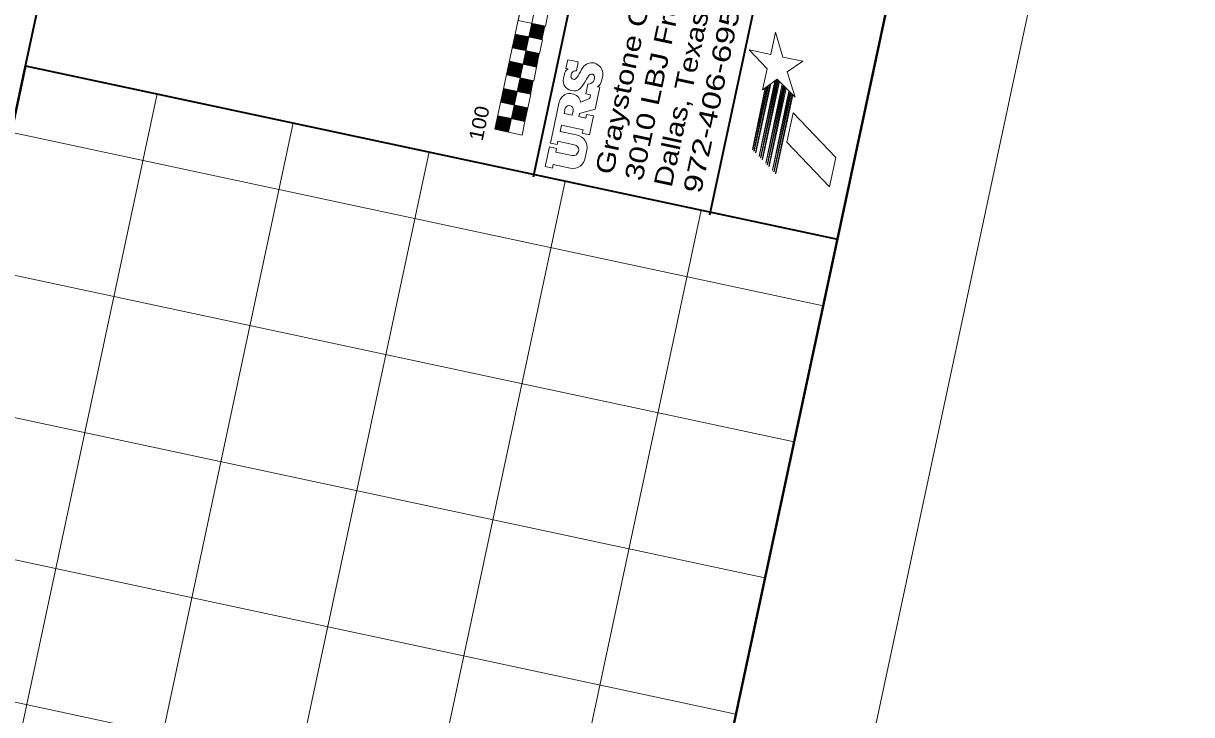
# Model space of a CAD drawing. Extents: x 2363411 to 2369126, y 6976878 to 6988319.
# Drawn here: x 2368286 to 2369126, y 6986411 to 6986908 of the extents above; entities that cross this region are included whole.
import ezdxf
from ezdxf.enums import TextEntityAlignment as Align

# ---------------------------------------------------------------- set-up
doc = ezdxf.new("R2010")
doc.units = 0
doc.header["$LTSCALE"] = 2
for name, color, linetype, lineweight in [('40', 7, 'Continuous', 13), ('62', 7, 'Continuous', 13), ('63', 7, 'Continuous', 13)]:
    doc.layers.add(name, color=color, linetype=linetype, lineweight=lineweight)

msp = doc.modelspace()

# ---------------------------------------------------------------- linework, layer by layer
at = {"layer": '40'}
for p, q in [((2367492.078, 6986997.24), (2368861.236, 6986704.691)), ((2367471.182, 6986899.443), (2368840.34, 6986606.896)), ((2368382.492, 6986857.104), (2366502.254, 6978057.311)), ((2368480.289, 6986836.208), (2366600.051, 6978036.415)), ((2368578.086, 6986815.312), (2366697.848, 6978015.519)), ((2367450.286, 6986801.645), (2368819.444, 6986509.099)), ((2368675.884, 6986794.415), (2366795.645, 6977994.623)), ((2368773.68, 6986773.519), (2366893.442, 6977973.727)), ((2367429.39, 6986703.849), (2368798.548, 6986411.302)), ((2367408.493, 6986606.051), (2368777.652, 6986313.505))]:
    msp.add_line(p, q, dxfattribs=at)
at = {"layer": '62', "lineweight": 35}
for p, q in [((2368287.795, 6986877.338), (2368423.826, 6987513.987)), ((2368788.776, 6987433.781), (2368652.739, 6986797.1)), ((2368862.364, 6987157.099), (2368779.65, 6986769.983)), ((2368287.795, 6986877.338), (2368871.478, 6986752.623))]:
    msp.add_line(p, q, dxfattribs=at)
at = {"layer": '62'}
for p, q in [((2369126.202, 6987466.173), (2366932.108, 6977197.487)), ((2368625.251, 6986831.589), (2368708.843, 6987222.813)), ((2368635.032, 6986829.5), (2368718.624, 6987220.723)), ((2368649.671, 6986897.96), (2368651.761, 6986907.742)), ((2368650.16, 6986897.857), (2368652.25, 6986907.637)), ((2368650.649, 6986897.751), (2368652.739, 6986907.534)), ((2368651.138, 6986897.648), (2368653.228, 6986907.429)), ((2368651.627, 6986897.542), (2368653.717, 6986907.324)), ((2368652.116, 6986897.439), (2368654.206, 6986907.22)), ((2368652.605, 6986897.334), (2368654.695, 6986907.116)), ((2368653.094, 6986897.229), (2368655.184, 6986907.011)), ((2368653.583, 6986897.124), (2368655.673, 6986906.906)), ((2368654.072, 6986897.02), (2368656.162, 6986906.802)), ((2368654.561, 6986896.916), (2368656.651, 6986906.698)), ((2368655.05, 6986896.812), (2368657.14, 6986906.593)), ((2368655.539, 6986896.706), (2368657.629, 6986906.489)), ((2368656.028, 6986896.603), (2368658.118, 6986906.385)), ((2368656.518, 6986896.498), (2368658.608, 6986906.279)), ((2368657.007, 6986896.394), (2368659.097, 6986906.175)), ((2368657.495, 6986896.289), (2368659.586, 6986906.07)), ((2368657.984, 6986896.184), (2368660.075, 6986905.966)), ((2368658.473, 6986896.081), (2368660.564, 6986905.861)), ((2368658.963, 6986895.975), (2368661.053, 6986905.757)), ((2368637.801, 6986890.269), (2368639.89, 6986900.051)), ((2368638.29, 6986890.165), (2368640.38, 6986899.946)), ((2368638.781, 6986890.06), (2368640.87, 6986899.841)), ((2368639.27, 6986889.956), (2368641.358, 6986899.736)), ((2368639.758, 6986889.851), (2368641.848, 6986899.632)), ((2368639.88, 6986900.053), (2368649.66, 6986897.963)), ((2368640.247, 6986889.747), (2368642.337, 6986899.528)), ((2368640.735, 6986889.643), (2368642.826, 6986899.423)), ((2368641.225, 6986889.538), (2368643.315, 6986899.318)), ((2368641.714, 6986889.434), (2368643.804, 6986899.215)), ((2368642.203, 6986889.33), (2368644.293, 6986899.109)), ((2368642.692, 6986889.224), (2368644.782, 6986899.006)), ((2368643.18, 6986889.12), (2368645.272, 6986898.901)), ((2368643.67, 6986889.015), (2368645.76, 6986898.796)), ((2368644.159, 6986888.912), (2368646.249, 6986898.691)), ((2368644.648, 6986888.806), (2368646.738, 6986898.587)), ((2368645.137, 6986888.702), (2368647.227, 6986898.483)), ((2368645.626, 6986888.598), (2368647.716, 6986898.378)), ((2368646.115, 6986888.493), (2368648.205, 6986898.273)), ((2368646.604, 6986888.389), (2368648.694, 6986898.17)), ((2368647.093, 6986888.285), (2368649.183, 6986898.064)), ((2368649.659, 6986897.964), (2368659.44, 6986895.874)), ((2368649.659, 6986897.963), (2368659.441, 6986895.874)), ((2368637.79, 6986890.272), (2368647.569, 6986888.182)), ((2368645.815, 6986878.331), (2368647.906, 6986888.111)), ((2368646.305, 6986878.225), (2368648.395, 6986888.007)), ((2368646.793, 6986878.121), (2368648.884, 6986887.903)), ((2368647.282, 6986878.017), (2368649.373, 6986887.798)), ((2368647.772, 6986877.912), (2368649.862, 6986887.694)), ((2368648.26, 6986877.807), (2368650.352, 6986887.589)), ((2368648.75, 6986877.703), (2368650.84, 6986887.483)), ((2368649.239, 6986877.598), (2368651.329, 6986887.38)), ((2368649.727, 6986877.494), (2368651.818, 6986887.275)), ((2368650.217, 6986877.389), (2368652.307, 6986887.171)), ((2368650.706, 6986877.286), (2368652.797, 6986887.066)), ((2368651.195, 6986877.18), (2368653.284, 6986886.962)), ((2368651.684, 6986877.077), (2368653.773, 6986886.859)), ((2368652.172, 6986876.97), (2368654.262, 6986886.753)), ((2368652.662, 6986876.866), (2368654.752, 6986886.648)), ((2368653.152, 6986876.762), (2368655.242, 6986886.544)), ((2368653.641, 6986876.658), (2368655.73, 6986886.439)), ((2368654.13, 6986876.553), (2368656.219, 6986886.336)), ((2368654.62, 6986876.448), (2368656.709, 6986886.23)), ((2368655.108, 6986876.344), (2368657.198, 6986886.127)), ((2368633.944, 6986870.639), (2368636.036, 6986880.419)), ((2368634.434, 6986870.534), (2368636.524, 6986880.315)), ((2368634.924, 6986870.429), (2368637.014, 6986880.21)), ((2368635.414, 6986870.326), (2368637.504, 6986880.105)), ((2368635.699, 6986880.492), (2368645.48, 6986878.401)), ((2368635.902, 6986870.22), (2368637.991, 6986880.001)), ((2368636.391, 6986870.117), (2368638.48, 6986879.898)), ((2368636.88, 6986870.012), (2368638.97, 6986879.793)), ((2368637.369, 6986869.907), (2368639.459, 6986879.689)), ((2368637.858, 6986869.804), (2368639.948, 6986879.584)), ((2368638.347, 6986869.699), (2368640.436, 6986879.479)), ((2368638.836, 6986869.594), (2368640.925, 6986879.375)), ((2368639.325, 6986869.489), (2368641.415, 6986879.27)), ((2368639.814, 6986869.385), (2368641.904, 6986879.166)), ((2368640.303, 6986869.281), (2368642.393, 6986879.061)), ((2368640.792, 6986869.176), (2368642.882, 6986878.956)), ((2368641.281, 6986869.072), (2368643.371, 6986878.853)), ((2368641.77, 6986868.968), (2368643.86, 6986878.748)), ((2368642.258, 6986868.862), (2368644.348, 6986878.643)), ((2368642.747, 6986868.759), (2368644.838, 6986878.538)), ((2368643.236, 6986868.653), (2368645.326, 6986878.434)), ((2368645.48, 6986878.402), (2368655.26, 6986876.312)), ((2368645.48, 6986878.401), (2368655.261, 6986876.312)), ((2368633.61, 6986870.71), (2368643.391, 6986868.62)), ((2368641.484, 6986858.802), (2368643.574, 6986868.581)), ((2368641.973, 6986858.697), (2368644.063, 6986868.477)), ((2368642.463, 6986858.593), (2368644.551, 6986868.372)), ((2368642.951, 6986858.488), (2368645.041, 6986868.268)), ((2368643.441, 6986858.384), (2368645.53, 6986868.163)), ((2368643.93, 6986858.279), (2368646.019, 6986868.059)), ((2368644.418, 6986858.175), (2368646.508, 6986867.954)), ((2368644.908, 6986858.07), (2368646.997, 6986867.85)), ((2368645.396, 6986857.966), (2368647.488, 6986867.746)), ((2368645.886, 6986857.861), (2368647.974, 6986867.641)), ((2368646.375, 6986857.757), (2368648.463, 6986867.537)), ((2368646.864, 6986857.653), (2368648.952, 6986867.432)), ((2368674.504, 6986868.119), (2368675.201, 6986871.38)), ((2368680.139, 6986870.917), (2368679.996, 6986870.246)), ((2368696.757, 6986867.48), (2368696.969, 6986868.663)), ((2368702.813, 6986870.319), (2368702.117, 6986867.058)), ((2368629.615, 6986851.112), (2368631.704, 6986860.892)), ((2368630.104, 6986851.007), (2368632.193, 6986860.787)), ((2368630.594, 6986850.902), (2368632.682, 6986860.683)), ((2368631.083, 6986850.798), (2368633.172, 6986860.578)), ((2368631.519, 6986860.931), (2368641.3, 6986858.842)), ((2368631.572, 6986850.692), (2368633.66, 6986860.473)), ((2368632.06, 6986850.588), (2368634.149, 6986860.369)), ((2368632.549, 6986850.484), (2368634.639, 6986860.265)), ((2368633.038, 6986850.38), (2368635.127, 6986860.161)), ((2368633.526, 6986850.276), (2368635.617, 6986860.055)), ((2368634.015, 6986850.171), (2368636.106, 6986859.952)), ((2368634.505, 6986850.067), (2368636.594, 6986859.847)), ((2368634.993, 6986849.962), (2368637.084, 6986859.743)), ((2368635.483, 6986849.857), (2368637.573, 6986859.638)), ((2368635.971, 6986849.752), (2368638.062, 6986859.533)), ((2368636.46, 6986849.649), (2368638.551, 6986859.428)), ((2368636.95, 6986849.543), (2368639.04, 6986859.324)), ((2368637.438, 6986849.439), (2368639.529, 6986859.22)), ((2368637.928, 6986849.335), (2368640.018, 6986859.115)), ((2368638.417, 6986849.231), (2368640.507, 6986859.01)), ((2368647.353, 6986857.548), (2368649.441, 6986867.328)), ((2368647.842, 6986857.443), (2368649.931, 6986867.224)), ((2368648.332, 6986857.34), (2368650.42, 6986867.119)), ((2368648.82, 6986857.234), (2368650.91, 6986867.014)), ((2368649.309, 6986857.131), (2368651.398, 6986866.909)), ((2368649.798, 6986857.025), (2368651.887, 6986866.805)), ((2368650.287, 6986856.921), (2368652.377, 6986866.7)), ((2368650.777, 6986856.816), (2368652.865, 6986866.596)), ((2368629.431, 6986851.15), (2368639.21, 6986849.06)), ((2368638.906, 6986849.126), (2368640.996, 6986858.907)), ((2368641.3, 6986858.841), (2368651.082, 6986856.751)), ((2368641.301, 6986858.839), (2368651.081, 6986856.749)), ((2368637.544, 6986839.189), (2368639.633, 6986848.969)), ((2368638.033, 6986839.085), (2368640.122, 6986848.863)), ((2368638.522, 6986838.98), (2368640.612, 6986848.76)), ((2368639.011, 6986838.876), (2368641.1, 6986848.655)), ((2368639.5, 6986838.771), (2368641.59, 6986848.552)), ((2368639.989, 6986838.668), (2368642.079, 6986848.446)), ((2368640.478, 6986838.561), (2368642.567, 6986848.342)), ((2368640.967, 6986838.458), (2368643.057, 6986848.236)), ((2368641.456, 6986838.353), (2368643.545, 6986848.132)), ((2368641.945, 6986838.248), (2368644.034, 6986848.029)), ((2368642.434, 6986838.144), (2368644.524, 6986847.924)), ((2368642.924, 6986838.04), (2368645.012, 6986847.819)), ((2368643.413, 6986837.935), (2368645.502, 6986847.715)), ((2368643.903, 6986837.83), (2368645.992, 6986847.61)), ((2368644.39, 6986837.725), (2368646.481, 6986847.507)), ((2368644.88, 6986837.622), (2368646.97, 6986847.4)), ((2368645.369, 6986837.516), (2368647.459, 6986847.297)), ((2368645.859, 6986837.413), (2368647.947, 6986847.192)), ((2368646.347, 6986837.307), (2368648.436, 6986847.088)), ((2368646.836, 6986837.203), (2368648.925, 6986846.984)), ((2368674.979, 6986843.05), (2368675.766, 6986846.731)), ((2368625.672, 6986831.498), (2368627.764, 6986841.28)), ((2368626.164, 6986831.395), (2368628.253, 6986841.175)), ((2368626.652, 6986831.289), (2368628.742, 6986841.071)), ((2368627.141, 6986831.186), (2368629.231, 6986840.965)), ((2368627.342, 6986841.369), (2368637.121, 6986839.279)), ((2368627.63, 6986831.08), (2368629.72, 6986840.861)), ((2368628.119, 6986830.977), (2368630.209, 6986840.756)), ((2368628.608, 6986830.871), (2368630.698, 6986840.652)), ((2368629.097, 6986830.767), (2368631.187, 6986840.548)), ((2368629.586, 6986830.663), (2368631.676, 6986840.443)), ((2368630.075, 6986830.558), (2368632.165, 6986840.338)), ((2368630.564, 6986830.453), (2368632.654, 6986840.234)), ((2368631.053, 6986830.349), (2368633.142, 6986840.13)), ((2368631.542, 6986830.244), (2368633.631, 6986840.026)), ((2368632.031, 6986830.141), (2368634.12, 6986839.921)), ((2368632.52, 6986830.035), (2368634.609, 6986839.817)), ((2368633.009, 6986829.932), (2368635.099, 6986839.713)), ((2368633.498, 6986829.827), (2368635.587, 6986839.608)), ((2368633.986, 6986829.722), (2368636.077, 6986839.504)), ((2368634.475, 6986829.618), (2368636.565, 6986839.398)), ((2368634.964, 6986829.513), (2368637.054, 6986839.295)), ((2368637.121, 6986839.279), (2368646.902, 6986837.19)), ((2368625.251, 6986831.589), (2368635.032, 6986829.5)), ((2368685.324, 6986815.762), (2368685.504, 6986816.604)), ((2368691.346, 6986816.633), (2368690.183, 6986811.205))]:
    msp.add_line(p, q, dxfattribs=at)
at = {"layer": '62', "lineweight": 40}
for p, q in [((2369007.509, 6987389.272), (2366855.207, 6977316.18)), ((2368287.795, 6986877.338), (2368278.342, 6986833.097))]:
    msp.add_line(p, q, dxfattribs=at)
at = {"layer": '62'}
for points in [[(2368661.531, 6986905.653), (2368663.62, 6986915.434), (2368644.059, 6986919.615), (2368641.97, 6986909.833)], [(2368808.187, 6986888.668), (2368820.942, 6986874.996), (2368817.737, 6986859.988), (2368828.121, 6986867.634), (2368841.046, 6986854.66), (2368835.463, 6986872.979), (2368846.561, 6986880.469), (2368832.247, 6986883.526), (2368826.968, 6986901.435), (2368823.547, 6986885.386)], [(2368657.352, 6986886.093), (2368659.441, 6986895.874), (2368639.88, 6986900.053), (2368637.79, 6986890.272)], [(2368653.172, 6986866.532), (2368655.261, 6986876.312), (2368635.699, 6986880.492), (2368633.61, 6986870.71)], [(2368816.227, 6986811.126), (2368827.967, 6986867.489), (2368828.121, 6986867.62), (2368828.663, 6986867.072), (2368816.401, 6986810.989)], [(2368648.992, 6986846.97), (2368651.082, 6986856.751), (2368631.519, 6986860.931), (2368629.431, 6986851.15)], [(2368810.447, 6986817.185), (2368819.696, 6986861.415), (2368820.449, 6986861.997), (2368810.613, 6986817.048)], [(2368811.534, 6986816.051), (2368821.24, 6986862.563), (2368822.028, 6986863.132), (2368811.669, 6986815.897)], [(2368812.7, 6986814.827), (2368822.945, 6986863.816), (2368823.715, 6986864.377), (2368812.857, 6986814.709)], [(2368815.158, 6986812.266), (2368826.431, 6986866.383), (2368827.314, 6986867.015), (2368815.319, 6986812.124)], [(2368817.404, 6986809.926), (2368829.219, 6986866.538), (2368829.849, 6986865.898), (2368817.565, 6986809.809)], [(2368819.966, 6986807.229), (2368831.821, 6986863.928), (2368832.428, 6986863.316), (2368820.111, 6986807.089)], [(2368821.033, 6986806.082), (2368832.902, 6986862.826), (2368833.496, 6986862.234), (2368821.191, 6986805.966)], [(2368822.195, 6986804.891), (2368834.069, 6986861.652), (2368834.669, 6986861.045), (2368822.363, 6986804.749)], [(2368824.769, 6986802.194), (2368836.652, 6986859.065), (2368837.223, 6986858.483), (2368824.921, 6986802.053)], [(2368825.816, 6986801.057), (2368837.738, 6986857.981), (2368838.301, 6986857.404), (2368825.986, 6986800.92)], [(2368827.002, 6986799.862), (2368838.899, 6986856.8), (2368839.472, 6986856.209), (2368827.134, 6986799.715)], [(2368835.13, 6986822.423), (2368865.823, 6986790.319), (2368870.295, 6986811.251), (2368839.594, 6986843.343)], [(2368644.811, 6986827.409), (2368646.902, 6986837.19), (2368627.342, 6986841.369), (2368625.251, 6986831.589)]]:
    msp.add_lwpolyline(points, close=True, dxfattribs=at)
for points in [[(2368677.655, 6986874.788), (2368677.705, 6986875.024), (2368676.37, 6986875.309), (2368677.719, 6986881.62), (2368685.19, 6986880.024), (2368683.842, 6986873.713)], [(2368698.994, 6986862.226), (2368700.677, 6986861.867), (2368697.306, 6986846.089), (2368686.185, 6986842.965), (2368685.713, 6986840.757), (2368690.554, 6986839.722), (2368691.116, 6986842.352), (2368696.272, 6986841.25), (2368693.373, 6986827.681), (2368688.111, 6986828.805), (2368688.628, 6986831.225), (2368673.159, 6986834.53), (2368672.193, 6986830.007), (2368683.768, 6986827.534)], [(2368686.705, 6986851.163), (2368693.46, 6986853.84), (2368694.022, 6986856.469), (2368690.655, 6986857.189), (2368692.138, 6986864.131)], [(2368682.262, 6986820.486), (2368670.581, 6986822.982), (2368670.087, 6986820.668), (2368665.141, 6986821.725), (2368671.209, 6986850.125)], [(2368681.524, 6986844.841), (2368680.872, 6986841.791), (2368674.979, 6986843.05)], [(2368679.425, 6986803.604), (2368667.113, 6986806.235), (2368666.574, 6986803.71), (2368661.417, 6986804.812), (2368664.429, 6986818.907), (2368669.585, 6986817.805), (2368669.046, 6986815.281), (2368680.937, 6986812.74)]]:
    msp.add_lwpolyline(points, dxfattribs=at)
for centre, radius, start, end in [((2368839.367, 6986785.496), 175.955, 149.05369, 151.29016), ((2368695.045, 6986871.417), 8.012, 78.41387, 145.29553), ((2368694.654, 6986871.295), 8.218, 353.17901, 75.91117), ((2368681.72, 6986866.62), 7.37, 168.2663, 257.09196), ((2368680.286, 6986870.306), 5.198, 120.41428, 168.07793), ((2368682.092, 6986869.691), 2.168, 165.16372, 258.08931), ((2368683.431, 6986870.407), 3.331, 82.91529, 171.20234), ((2368682.207, 6986869.137), 1.665, 250.24926, 277.37841), ((2368680.205, 6986872.401), 5.392, 294.26931, 333.80667), ((2368715.127, 6986853.824), 27.684, 144.92425, 151.42581), ((2368692.417, 6986868.606), 4.484, 266.43013, 345.46077), ((2368694.881, 6986868.584), 2.67, 74.36667, 154.52723), ((2368694.761, 6986869.072), 2.246, 349.50434, 68.02942), ((2368682.047, 6986865.696), 6.564, 252.50367, 317.59453), ((2368670.456, 6986876.617), 22.489, 316.96642, 334.86563), ((2368695.371, 6986867.993), 6.81, 302.13459, 352.11286), ((2368681.195, 6986848.078), 10.193, 123.35717, 168.41551), ((2368678.82, 6986848.948), 8.299, 75.90104, 112.9089), ((2368680.245, 6986850.533), 6.491, 5.5733, 84.72213), ((2368678.612, 6986845.51), 3.097, 69.91263, 156.76172), ((2368678.829, 6986845.714), 2.833, 342.05224, 72.61061), ((2368682.384, 6986818.487), 9.152, 348.31197, 81.303), ((2368681.927, 6986816.911), 3.591, 355.09044, 84.63511), ((2368681.305, 6986812.357), 8.952, 257.88198, 352.60463), ((2368681.588, 6986816.492), 3.807, 260.16836, 348.95723)]:
    msp.add_arc(centre, radius, start, end, dxfattribs=at)
at = {"layer": '63', "lineweight": 35}
for q in [(2368423.826, 6987513.987), (2368871.478, 6986752.623)]:
    msp.add_line((2368287.795, 6986877.338), q, dxfattribs=at)
at = {"layer": '63'}
for p, q in [((2369126.202, 6987466.173), (2366932.108, 6977197.487)), ((2367492.078, 6986997.24), (2368861.236, 6986704.691)), ((2367471.182, 6986899.443), (2368840.34, 6986606.896)), ((2368382.492, 6986857.104), (2366502.254, 6978057.311)), ((2368480.289, 6986836.208), (2366600.051, 6978036.415)), ((2368578.086, 6986815.312), (2366697.848, 6978015.519)), ((2367450.286, 6986801.645), (2368819.444, 6986509.099)), ((2368675.884, 6986794.415), (2366795.645, 6977994.623)), ((2368773.68, 6986773.519), (2366893.442, 6977973.727)), ((2367429.39, 6986703.849), (2368798.548, 6986411.302)), ((2367408.493, 6986606.051), (2368777.652, 6986313.505))]:
    msp.add_line(p, q, dxfattribs=at)
at = {"layer": '63', "lineweight": 40}
msp.add_line((2369007.509, 6987389.272), (2366855.207, 6977316.18), dxfattribs=at)

# ---------------------------------------------------------------- texts
at = {"layer": '62'}
for s, width, p in [('3010 LBJ Freeway, Suite 1300', 1.25, (2368731.217, 6986793.8)), ('Dallas, Texas 75234', 1.2, (2368752.289, 6986789.297)), ('Graystone Centre', 1.25, (2368710.144, 6986798.303)), ('972-406-6950', 1.35, (2368773.363, 6986784.795))]:
    msp.add_text(s, height=13.22, rotation=77.939, dxfattribs=dict(at, width=width)).set_placement(p)
at = {"layer": '62', "width": 1.1}
msp.add_text('100', height=10.2, rotation=77.939, dxfattribs=at).set_placement((2368618.943, 6986834.882), align=Align.CENTER)

doc.saveas('drawing.dxf')
